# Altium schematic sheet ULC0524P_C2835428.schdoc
size 127 x 101 mm
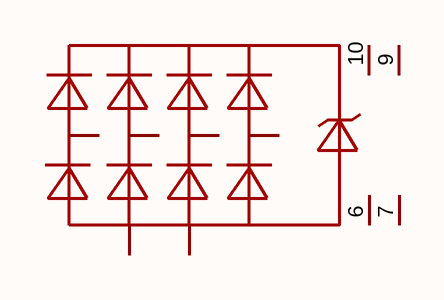
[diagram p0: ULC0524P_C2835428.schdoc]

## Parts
D?  ulc0524p_c2835428  [DFN2510-10_L2.5-W1.0-P0.50-BL]  (value not drawn)

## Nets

Not connected (* = marked no-connect by the designer): D? 1(K) 2(K) 3(GND) 4(K) 5(K) 6(NC) 7(NC) 8(GND) 9(NC) 10(NC)

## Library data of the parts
D? = ulc0524p_c2835428: 极性:单向;反向截止电压(Vrwm):5V;钳位电压:13V;峰值脉冲功率(Ppp):70W@8/20us;击穿电压:7.5V;; Manufacturer: TECH PUBLIC(台舟); AddInBom: yes; ModelId: 55525fa8fc914f7c8ffcb10749ea5f73; ModelName: DFN-10_L2.5-W1.0-H0.5-P0.50; ModelTransform: 40.1574,98.425,0,90,0,0,0,0,0; Polarity: 单向; Reverse Stand-Off Voltage (Vrwm): 5V; Clamping Voltage: 13V; Voltage - Breakdown: 7.5V; Reverse Leakage Current (Ir): 10nA; Number of Channels: 四路; level of protection: IEC 61000-4-4；IEC 61000-4-5；IEC 61000-4-2; Type: ESD; Junction Capacitance: 0.3pF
